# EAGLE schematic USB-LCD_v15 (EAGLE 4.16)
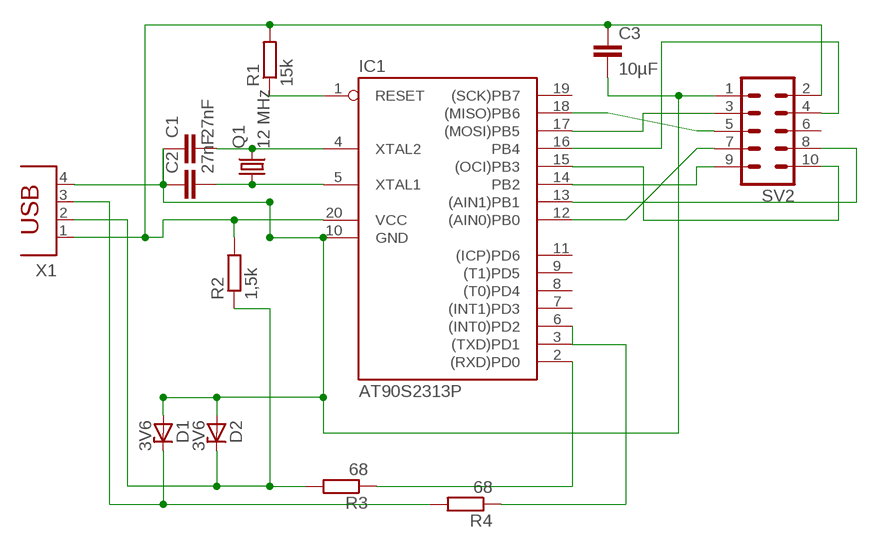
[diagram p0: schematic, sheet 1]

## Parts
C1  27nF  C2,5-3  [C2.5-3]
C2  27nF  C2,5-3  [C2.5-3]
C3  10µF  C2.5/6  [C2.5-6]
D1  3V6  ZENER-DIODEDO34-7  [DO34Z7]
D2  3V6  ZENER-DIODEDO34-7  [DO34Z7]
IC1  AT90S2313P  [DIL20]
Q1  12 MHz  CRYSTALHC49S  [HC49/S]
R1  15k  R-EU_0207/10  [0207/10]
R2  1,5k  R-EU_0207/10  [0207/10]
R3  68  R-EU_0207/10  [0207/10]
R4  68  R-EU_0207/10  [0207/10]
SV2  ML10  [ML10]
X1  PN61729  [PN61729]

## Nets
N$1: D1.C R4.2 X1.3
N$2: D2.C R2.1 R3.2 X1.2
N$3: IC1.16(PB4) SV2.4
N$4: C1.1 C2.1 C3.2 D1.A D2.A IC1.10(GND) SV2.1 X1.4
N$5: C1.2 IC1.4(XTAL2) Q1.2
N$6: C2.2 IC1.5(XTAL1) Q1.1
N$7: C3.1 IC1.20(VCC) R1.2 R2.2 SV2.2 X1.1
N$8: IC1.17((MOSI)PB5) SV2.3
N$9: IC1.18((MISO)PB6) SV2.5
N$10: IC1.13((AIN1)PB1) SV2.8
N$11: IC1.12((AIN0)PB0) SV2.7
N$12: IC1.14(PB2) SV2.9
N$13: IC1.15((OCI)PB3) SV2.10
N$14: IC1.2((RXD)PD0) R3.1
N$15: IC1.3((TXD)PD1) IC1.6((INT0)PD2) R4.1
N$16: IC1.1(RESET) R1.1
Unconnected: IC1.7((INT1)PD3) IC1.8((T0)PD4) IC1.9((T1)PD5) IC1.11((ICP)PD6) IC1.19((SCK)PB7) SV2.6

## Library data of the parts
C1-C3 = capacitor-wima:C: CAPACITOR
D1 D2 = diode:ZENER-DIODE: Z-Diode
IC1 = atmel:AT90S2313: MICROCONTROLLER 2 Kbytes FLASH 128 bytes SRAM 128 bytes EEPROM UART
Q1 = crystal:CRYSTAL: CRYSTAL
R1-R4 = rcl:R-EU_: RESISTOR, European symbol
SV2 = con-harting-ml:ML10: HARTING
X1 = con-berg:PN61729: BERG USB connector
